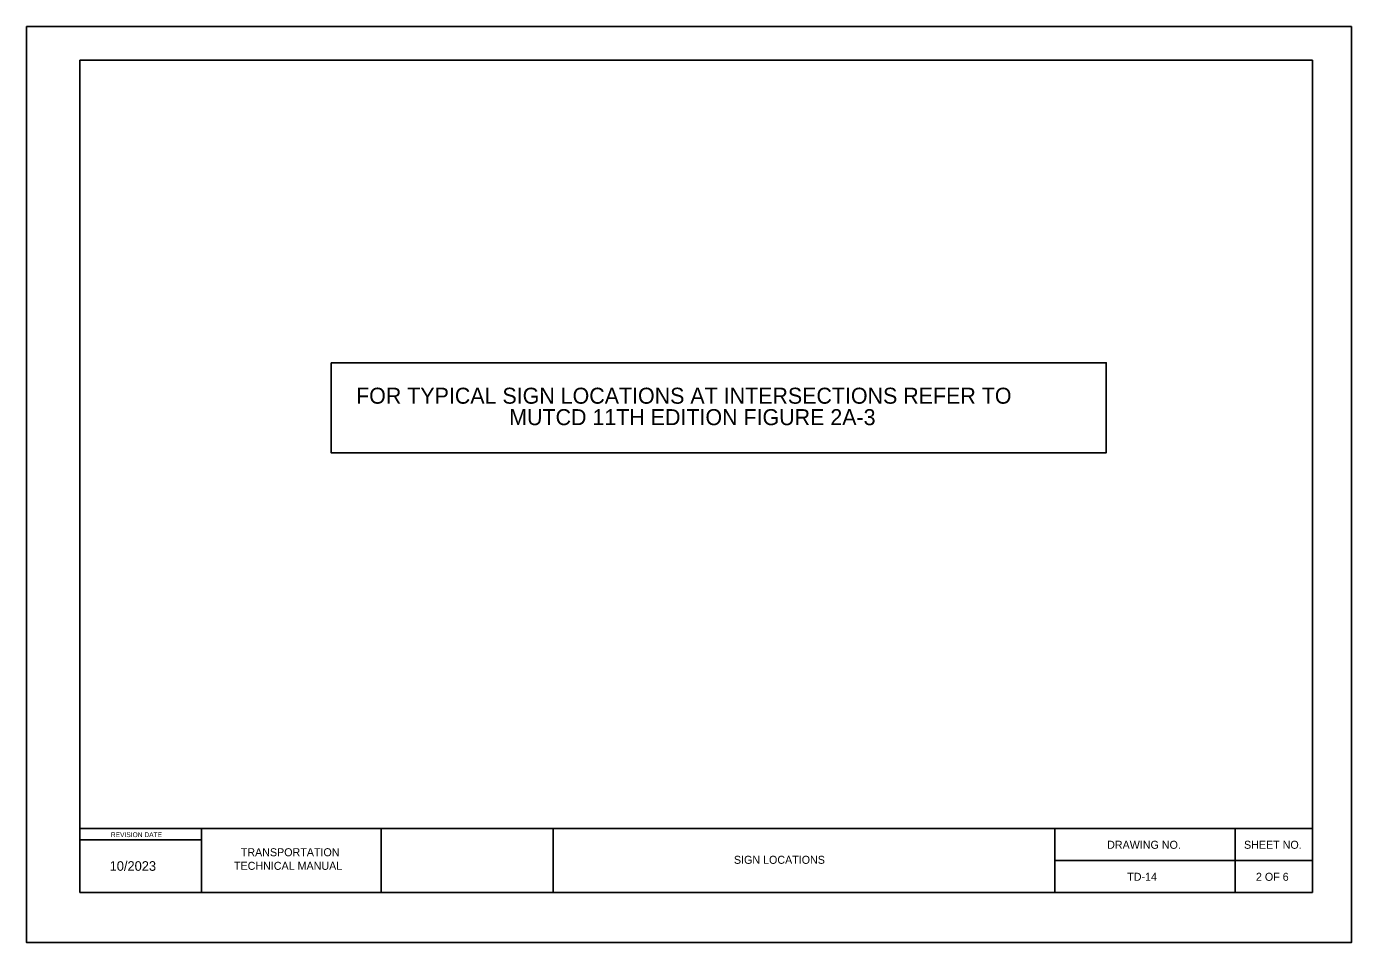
# Model space of a CAD drawing. Extents: x -14.6 to 39.7, y -12.4 to 25.1.
import ezdxf

# ---------------------------------------------------------------- set-up
doc = ezdxf.new("R2010")
doc.units = 0
for name, color, linetype in [('Default', 7, 'Continuous'), ('NonPlottingEle_dp', 7, 'Continuous'), ('SheetBorder_dp', 7, 'Continuous'), ('SheetLines_dp', 7, 'Continuous'), ('TextMinor', 7, 'Continuous')]:
    doc.layers.add(name, color=color, linetype=linetype)

msp = doc.modelspace()

# ---------------------------------------------------------------- linework, layer by layer
at = {"layer": 'Default'}
msp.add_lwpolyline([(-2.085, 11.359), (29.691, 11.359), (29.691, 7.669), (-2.085, 7.669)], close=True, dxfattribs=at)
at = {"layer": 'NonPlottingEle_dp'}
msp.add_lwpolyline([(38.12, 25.141), (-14.569, 25.141), (-14.569, -12.409), (39.74, -12.409), (39.74, 25.141)], close=True, dxfattribs=at)
at = {"layer": 'SheetBorder_dp'}
for p, q in [((-12.382, 23.76), (-12.382, -10.361)), ((-12.382, 23.76), (38.143, 23.76)), ((38.143, 23.76), (38.143, -10.361)), ((-12.382, -7.741), (38.143, -7.741)), ((-12.382, -10.361), (38.143, -10.361))]:
    msp.add_line(p, q, dxfattribs=at)
at = {"layer": 'SheetLines_dp'}
for p, q in [((-7.394, -7.736), (-7.394, -10.361)), ((-0.027, -7.736), (-0.027, -10.361)), ((7.017, -7.741), (7.017, -10.361)), ((27.582, -10.361), (27.582, -7.736)), ((34.972, -10.361), (34.972, -7.736)), ((-12.382, -8.196), (-7.394, -8.196)), ((27.582, -9.049), (38.143, -9.049))]:
    msp.add_line(p, q, dxfattribs=at)

# ---------------------------------------------------------------- texts
at = {"layer": 'TextMinor'}
for s, height, p in [('FOR TYPICAL SIGN LOCATIONS AT INTERSECTIONS REFER TO ', 0.65617, (-1.059, 9.678)), ('MUTCD 11TH EDITION FIGURE 2A-3 ', 0.65617, (5.216, 8.799)), ('REVISION DATE', 0.19685, (-11.112, -8.089)), ('TRANSPORTATION', 0.32808, (-5.786, -8.873)), ('DRAWING NO.', 0.32808, (29.724, -8.567)), ('SHEET NO.', 0.3281, (35.335, -8.567)), ('10/2023', 0.3937, (-11.162, -9.47)), ('TECHNICAL MANUAL', 0.32808, (-6.066, -9.43)), ('SIGN LOCATIONS', 0.32808, (14.427, -9.183)), ('TD-14', 0.3281, (30.548, -9.879)), ('2 OF 6 ', 0.3281, (35.824, -9.879))]:
    msp.add_text(s, height=height, dxfattribs=at).set_placement(p)

doc.saveas('drawing.dxf')
